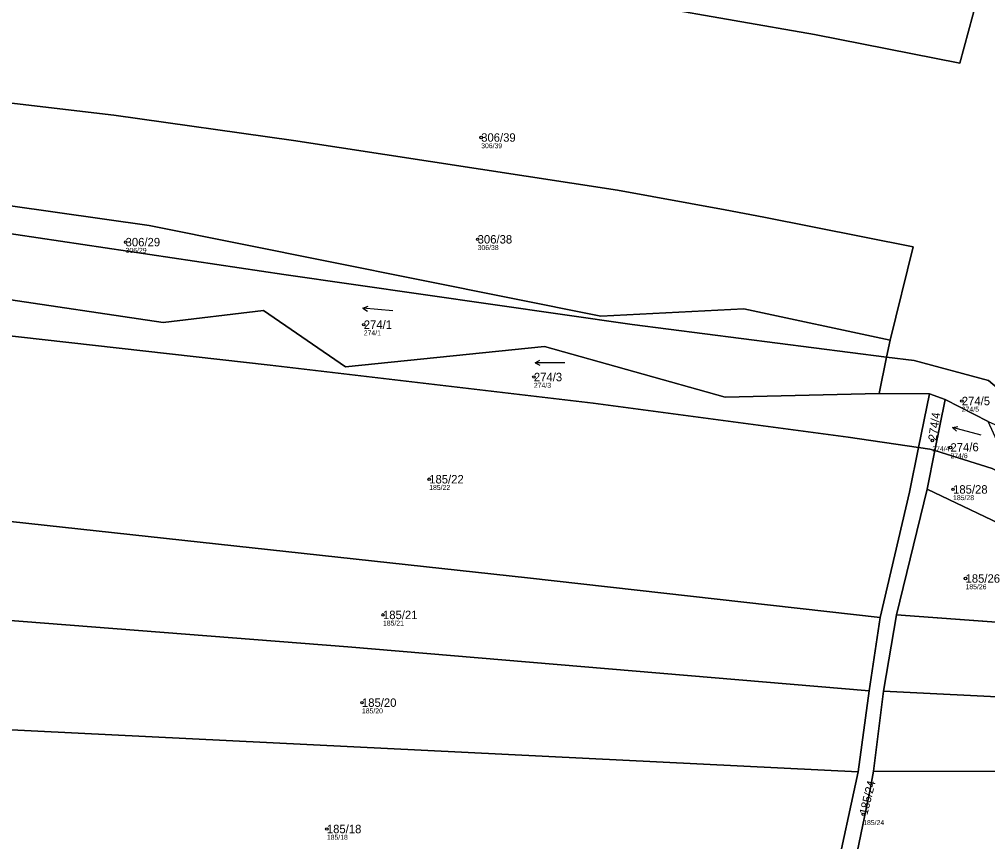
# Model space of a CAD drawing. Extents: x -732749 to -730903, y -1025757 to -1023435.
# Drawn here: x -732395.3 to -732200.2, y -1024211.9 to -1024046.3 of the extents above; entities that cross this region are included whole.
import ezdxf

# ---------------------------------------------------------------- set-up
doc = ezdxf.new("R2010")
doc.units = 0
for name, color, linetype in [('Definiční body', 7, 'Continuous'), ('Hranice parcel', 7, 'Continuous'), ('Parcelní čísla', 7, 'Continuous'), ('Polygon parcely', 7, 'Continuous'), ('Značky kultur', 7, 'Continuous')]:
    doc.layers.add(name, color=color, linetype=linetype)

msp = doc.modelspace()

# ---------------------------------------------------------------- linework, layer by layer
at = {"layer": 'Definiční body'}
for centre in [(-732302.25, -1024070.12), (-732373.88, -1024091.19), (-732302.96, -1024090.62), (-732325.9, -1024107.81), (-732291.63, -1024118.36), (-732205.43, -1024123.19), (-732211.38, -1024131.13), (-732207.71, -1024132.55), (-732312.72, -1024138.94), (-732207.19, -1024140.99), (-732204.68, -1024158.93), (-732322.03, -1024166.26), (-732326.27, -1024183.93), (-732225.29, -1024206.43), (-732333.34, -1024209.38)]:
    msp.add_circle(centre, 0.25, dxfattribs=at)
at = {"layer": 'Hranice parcel'}
for p, q in [((-732220.57, -1024114.34), (-732219.85, -1024110.9)), ((-732222.09, -1024121.66), (-732220.57, -1024114.34)), ((-732215.04, -1024115.05), (-732220.57, -1024114.34)), ((-732211.96, -1024121.76), (-732222.09, -1024121.66)), ((-732214.14, -1024132.54), (-732211.96, -1024121.76)), ((-732208.81, -1024122.87), (-732211.96, -1024121.76)), ((-732210.87, -1024133.18), (-732208.81, -1024122.87)), ((-732208.81, -1024122.87), (-732200.12, -1024127.3)), ((-732212.43, -1024140.96), (-732210.87, -1024133.18)), ((-732218.59, -1024166.23), (-732212.43, -1024140.96)), ((-732224.1, -1024181.55), (-732221.87, -1024166.76)), ((-732221.23, -1024181.59), (-732218.59, -1024166.23)), ((-732218.59, -1024166.23), (-732180.2, -1024169.07)), ((-732226.32, -1024197.87), (-732224.1, -1024181.55)), ((-732223.22, -1024197.72), (-732221.23, -1024181.59)), ((-732226.32, -1024197.87), (-732471.52, -1024185.74)), ((-732231.05, -1024219.9), (-732226.32, -1024197.87)), ((-732223.22, -1024197.72), (-732146.9, -1024197.88))]:
    msp.add_line(p, q, dxfattribs=at)
for points in [[(-732202.34, -1024042.17), (-732205.86, -1024055.13), (-732235.08, -1024049.36), (-732267.5, -1024043.76), (-732299.42, -1024038.33), (-732357.84, -1024028.95), (-732378.03, -1024025.33), (-732396.34, -1024022.32)], [(-732219.85, -1024110.9), (-732215.21, -1024092.17), (-732245.34, -1024086.16), (-732253.13, -1024084.68), (-732274.78, -1024080.72), (-732340.07, -1024070.7), (-732376.22, -1024065.6), (-732415.7, -1024060.98)], [(-732219.85, -1024110.9), (-732249.37, -1024104.65), (-732278.16, -1024106.13), (-732369.16, -1024087.86), (-732425.1, -1024079.95)], [(-732220.57, -1024114.34), (-732271.81, -1024107.75), (-732342, -1024097.72), (-732427.54, -1024084.98)], [(-732433.43, -1024097.16), (-732400.68, -1024102.28), (-732366.29, -1024107.38), (-732346.08, -1024104.97), (-732329.55, -1024116.28), (-732289.5, -1024112.2), (-732253.12, -1024122.4), (-732222.09, -1024121.66)], [(-732214.14, -1024132.54), (-732228.35, -1024130.5), (-732279.67, -1024123.6), (-732344.73, -1024115.99), (-732425.96, -1024106.85), (-732438.84, -1024104.03)], [(-732188.12, -1024129.1), (-732200.06, -1024119.06), (-732215.04, -1024115.05)], [(-732221.87, -1024166.76), (-732215.96, -1024141.56), (-732214.14, -1024132.54)], [(-732210.87, -1024133.18), (-732211.9, -1024132.86), (-732214.14, -1024132.54)], [(-732194.74, -1024139.09), (-732199.32, -1024136.75), (-732210.87, -1024133.18)], [(-732221.87, -1024166.76), (-732292.93, -1024158.78), (-732397.07, -1024147.47), (-732404.48, -1024147.09), (-732457.26, -1024141.11)], [(-732180.2, -1024169.07), (-732187.43, -1024157.93), (-732193.55, -1024149.96), (-732212.43, -1024140.96)], [(-732224.1, -1024181.55), (-732329.09, -1024172.69), (-732465.13, -1024162.11)], [(-732146.9, -1024197.88), (-732147.83, -1024196.26), (-732164.67, -1024184.46), (-732221.23, -1024181.59)], [(-732227.62, -1024219.53), (-732223.87, -1024201.39), (-732223.22, -1024197.72)]]:
    msp.add_lwpolyline(points, dxfattribs=at)
at = {"layer": 'Polygon parcely'}
for points in [[(-732202.34, -1024042.17), (-732229.16, -1024036.61), (-732269.63, -1024029.19), (-732343.34, -1024015.55), (-732388.67, -1024007.86), (-732396.34, -1024022.32), (-732378.03, -1024025.33), (-732357.84, -1024028.95), (-732299.42, -1024038.33), (-732267.5, -1024043.76), (-732235.08, -1024049.36), (-732205.86, -1024055.13)], [(-732245.34, -1024086.16), (-732253.13, -1024084.68), (-732274.78, -1024080.72), (-732340.07, -1024070.7), (-732376.22, -1024065.6), (-732415.7, -1024060.98), (-732417.43, -1024064.21), (-732425.1, -1024079.95), (-732369.16, -1024087.86), (-732278.16, -1024106.13), (-732249.37, -1024104.65), (-732219.85, -1024110.9), (-732215.21, -1024092.17)], [(-732220.57, -1024114.34), (-732219.85, -1024110.9), (-732249.37, -1024104.65), (-732278.16, -1024106.13), (-732369.16, -1024087.86), (-732425.1, -1024079.95), (-732427.54, -1024084.98), (-732342, -1024097.72), (-732271.81, -1024107.75)], [(-732346.08, -1024104.97), (-732329.55, -1024116.28), (-732289.5, -1024112.2), (-732253.12, -1024122.4), (-732222.09, -1024121.66), (-732220.57, -1024114.34), (-732271.81, -1024107.75), (-732342, -1024097.72), (-732427.54, -1024084.98), (-732432, -1024095.35), (-732433.43, -1024097.16), (-732400.68, -1024102.28), (-732366.29, -1024107.38)], [(-732211.96, -1024121.76), (-732222.09, -1024121.66), (-732253.12, -1024122.4), (-732289.5, -1024112.2), (-732329.55, -1024116.28), (-732346.08, -1024104.97), (-732366.29, -1024107.38), (-732400.68, -1024102.28), (-732433.43, -1024097.16), (-732438.84, -1024104.03), (-732425.96, -1024106.85), (-732344.73, -1024115.99), (-732279.67, -1024123.6), (-732228.35, -1024130.5), (-732214.14, -1024132.54)], [(-732425.96, -1024106.85), (-732438.84, -1024104.03), (-732448.27, -1024122.66), (-732457.26, -1024141.11), (-732404.48, -1024147.09), (-732397.07, -1024147.47), (-732292.93, -1024158.78), (-732221.87, -1024166.76), (-732215.96, -1024141.56), (-732214.14, -1024132.54), (-732228.35, -1024130.5), (-732279.67, -1024123.6), (-732344.73, -1024115.99)], [(-732215.04, -1024115.05), (-732220.57, -1024114.34), (-732222.09, -1024121.66), (-732211.96, -1024121.76), (-732208.81, -1024122.87), (-732200.12, -1024127.3), (-732185.85, -1024133.7), (-732187.17, -1024129.78), (-732188.12, -1024129.1), (-732200.06, -1024119.06)], [(-732208.81, -1024122.87), (-732211.96, -1024121.76), (-732214.14, -1024132.54), (-732211.9, -1024132.86), (-732210.87, -1024133.18)], [(-732194.74, -1024139.09), (-732200.12, -1024127.3), (-732208.81, -1024122.87), (-732210.87, -1024133.18), (-732199.32, -1024136.75)], [(-732150.14, -1024170.86), (-732154.77, -1024167.06), (-732178.22, -1024158.16), (-732191.29, -1024146.66), (-732194.74, -1024139.09), (-732199.32, -1024136.75), (-732210.87, -1024133.18), (-732212.43, -1024140.96), (-732193.55, -1024149.96), (-732187.43, -1024157.93), (-732180.2, -1024169.07)], [(-732457.26, -1024141.11), (-732460.72, -1024148.2), (-732462.41, -1024152.4), (-732465.13, -1024162.11), (-732329.09, -1024172.69), (-732224.1, -1024181.55), (-732221.87, -1024166.76), (-732292.93, -1024158.78), (-732397.07, -1024147.47), (-732404.48, -1024147.09)], [(-732193.55, -1024149.96), (-732212.43, -1024140.96), (-732218.59, -1024166.23), (-732180.2, -1024169.07), (-732187.43, -1024157.93)], [(-732224.1, -1024181.55), (-732329.09, -1024172.69), (-732465.13, -1024162.11), (-732466.28, -1024166.23), (-732471.52, -1024185.74), (-732226.32, -1024197.87)], [(-732150.14, -1024170.86), (-732180.2, -1024169.07), (-732218.59, -1024166.23), (-732221.23, -1024181.59), (-732164.67, -1024184.46), (-732147.83, -1024196.26), (-732146.9, -1024197.88), (-732139.9, -1024208.82), (-732137.04, -1024214.57), (-732134.91, -1024220.93), (-732132.68, -1024227.88), (-732128.79, -1024227.7), (-732126.8, -1024215.79), (-732126.09, -1024198.98), (-732133.17, -1024182.06)], [(-732221.23, -1024181.59), (-732223.22, -1024197.72), (-732146.9, -1024197.88), (-732147.83, -1024196.26), (-732164.67, -1024184.46)], [(-732471.52, -1024185.74), (-732473.69, -1024193.82), (-732477.34, -1024211.36), (-732477.92, -1024213.06), (-732410.01, -1024219.62), (-732316.84, -1024219.53), (-732275.68, -1024219.9), (-732231.05, -1024219.9), (-732226.32, -1024197.87)], [(-732146.9, -1024197.88), (-732223.22, -1024197.72), (-732223.87, -1024201.39), (-732227.62, -1024219.53), (-732137.04, -1024214.57), (-732139.9, -1024208.82)]]:
    msp.add_lwpolyline(points, close=True, dxfattribs=at)
for points in [[(-732202.34, -1024042.17), (-732205.86, -1024055.13), (-732235.08, -1024049.36), (-732267.5, -1024043.76)], [(-732415.7, -1024060.98), (-732376.22, -1024065.6), (-732340.07, -1024070.7), (-732274.78, -1024080.72), (-732253.13, -1024084.68), (-732245.34, -1024086.16), (-732215.21, -1024092.17), (-732219.85, -1024110.9), (-732220.57, -1024114.34), (-732215.04, -1024115.05), (-732200.06, -1024119.06), (-732188.12, -1024129.1), (-732187.17, -1024129.78), (-732187.98, -1024127.38), (-732180.69, -1024107.38), (-732173.65, -1024087.72), (-732162.24, -1024055.08), (-732168.56, -1024044.02)], [(-732227.62, -1024219.53), (-732223.87, -1024201.39), (-732223.22, -1024197.72), (-732221.23, -1024181.59), (-732218.59, -1024166.23), (-732212.43, -1024140.96), (-732210.87, -1024133.18), (-732211.9, -1024132.86), (-732214.14, -1024132.54), (-732215.96, -1024141.56), (-732221.87, -1024166.76), (-732224.1, -1024181.55), (-732226.32, -1024197.87), (-732231.05, -1024219.9)]]:
    msp.add_lwpolyline(points, dxfattribs=at)
at = {"layer": 'Značky kultur'}
for p, q in [((-732326.06, -1024104.48), (-732325.04, -1024104.06)), ((-732320.08, -1024105), (-732326.06, -1024104.48)), ((-732326.06, -1024104.48), (-732325.12, -1024105.06)), ((-732291.39, -1024115.49), (-732290.41, -1024114.99)), ((-732285.39, -1024115.49), (-732291.39, -1024115.49)), ((-732291.39, -1024115.49), (-732290.41, -1024115.99)), ((-732207.31, -1024128.54), (-732206.24, -1024128.31)), ((-732201.52, -1024130.09), (-732207.31, -1024128.54)), ((-732207.31, -1024128.54), (-732206.5, -1024129.28))]:
    msp.add_line(p, q, dxfattribs=at)

# ---------------------------------------------------------------- texts
at = {"layer": 'Definiční body'}
for s, p in [('306/39', (-732302.25, -1024072.28)), ('306/38', (-732302.96, -1024092.78)), ('306/29', (-732373.88, -1024093.35)), ('274/1', (-732325.9, -1024109.97)), ('274/3', (-732291.63, -1024120.52)), ('274/5', (-732205.43, -1024125.35)), ('274/4', (-732211.38, -1024133.29)), ('274/6', (-732207.71, -1024134.71)), ('185/22', (-732312.72, -1024141.1)), ('185/28', (-732207.19, -1024143.15)), ('185/26', (-732204.68, -1024161.09)), ('185/21', (-732322.03, -1024168.42)), ('185/20', (-732326.27, -1024186.09)), ('185/24', (-732225.29, -1024208.59)), ('185/18', (-732333.34, -1024211.54))]:
    msp.add_text(s, height=1, dxfattribs=at).set_placement(p)
at = {"layer": 'Parcelní čísla'}
for s, p in [('306/39', (-732302.25, -1024070.97)), ('306/38', (-732302.96, -1024091.47)), ('306/29', (-732373.88, -1024092.04)), ('274/1', (-732325.9, -1024108.66)), ('274/3', (-732291.63, -1024119.21)), ('274/5', (-732205.43, -1024124.04)), ('185/22', (-732312.72, -1024139.79)), ('185/28', (-732207.19, -1024141.84)), ('185/26', (-732204.68, -1024159.78)), ('185/21', (-732322.03, -1024167.11)), ('185/20', (-732326.27, -1024184.78)), ('185/18', (-732333.34, -1024210.23))]:
    msp.add_text(s, height=1.7, dxfattribs=at).set_placement(p)
for s, rotation, p in [('274/4', 82, (-732210.54, -1024131.25)), ('274/6', 1, (-732207.7, -1024133.4)), ('185/24', 76, (-732224.46, -1024206.64))]:
    msp.add_text(s, height=1.7, rotation=rotation, dxfattribs=at).set_placement(p)

doc.saveas('drawing.dxf')
